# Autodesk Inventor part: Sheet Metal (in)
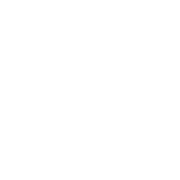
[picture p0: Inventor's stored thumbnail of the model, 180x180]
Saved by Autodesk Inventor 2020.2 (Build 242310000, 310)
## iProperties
Shininess: 64.0
Length Units: 11272
Angle Units: 11279
Time Units: 11290
Mass Units: 11286
Length Display Precision: 3
Angle Display Precision: 2
Compacted: True
Manager: www.cadconsulting.pl
Company: Fabian Stasiak CAD Consulting
Part Number: Sheet Metal (in)
Document SubType Name: Sheet Metal
Created: 2002-07
Material: Generic
Density: 1 g/cm^3
Sheet Metal Rule: Domyślny
Appearance: Default
Catalog Web Link: www.expertbooks.pl
Designer: F.Stasiak
Density: 0.0
Volumn: 0.0
Area: 0.0
PropertySet Name: Model Information
Control State: 0
Master: False
Checked Out: False
Subject: Zbiór ćwiczeń. Autodesk Inventor 2020. Kurs Professional
Author: F.Stasiak
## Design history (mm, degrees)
other parameters: "Thickness" = 3.048, "BendRadius" = 3.048 (= Thickness), "BendReliefWidth" = 3.048 (= Thickness), "BendReliefDepth" = 1.524 (= 0.5 x Thickness), "CornerReliefSize" = 12.192 (= 4 x Thickness), "SeamGap" = 0.00508, "MinimumRemnant" = 6.096 (= 2 x Thickness), "TransitionRadius" = 3.048 (= BendRadius), "JacobiRadiusSize" = 3.048 (= BendRadius), "GapSize" = 3.048 (= Thickness)
